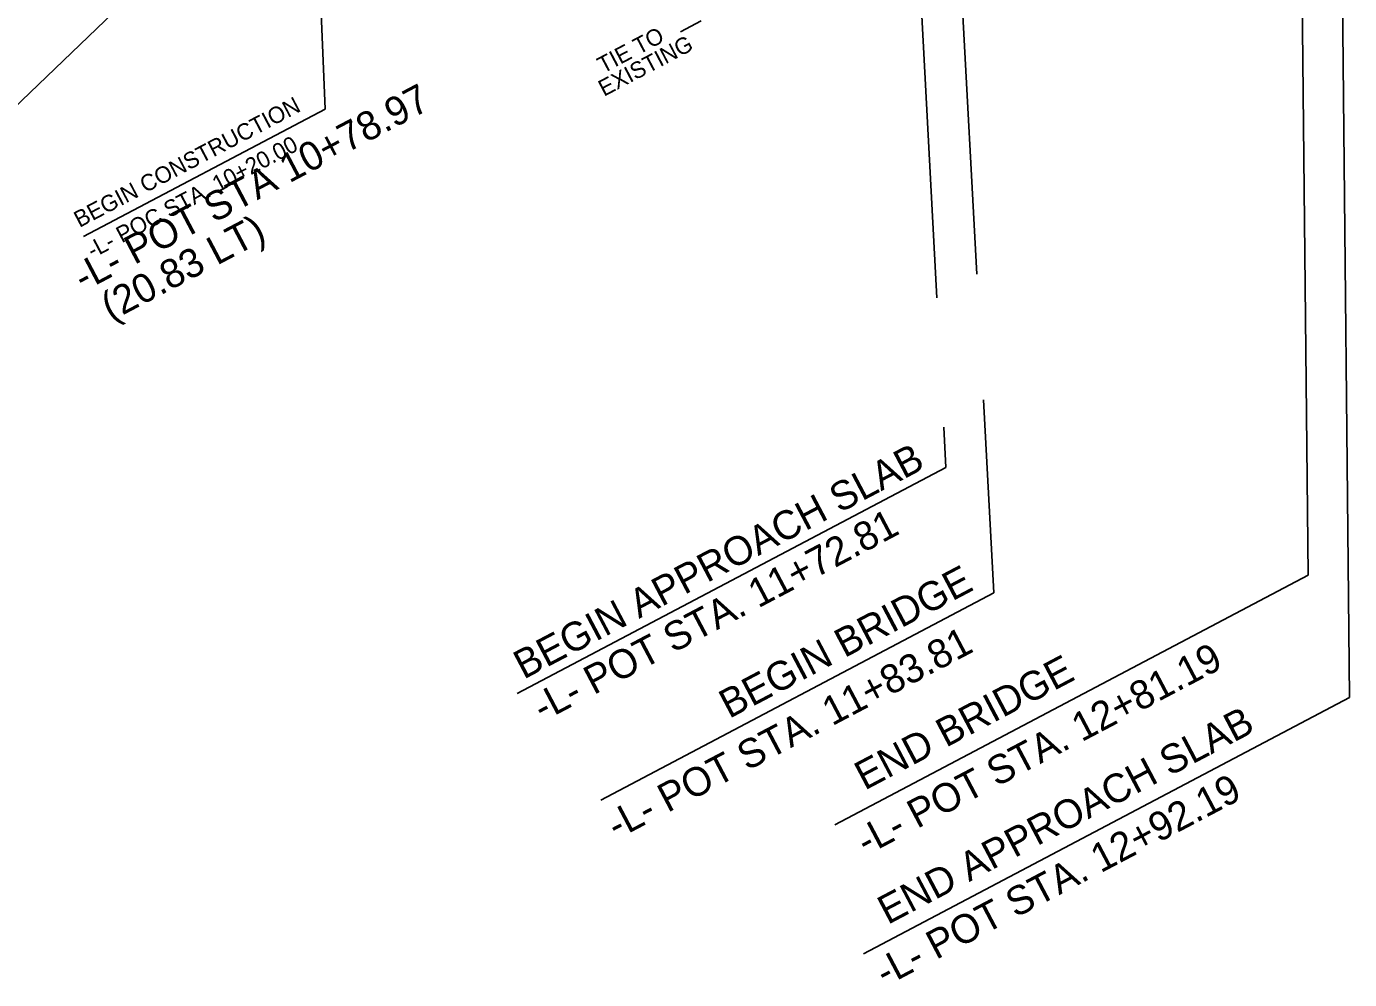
# Model space of a CAD drawing. Extents: x 1380803 to 1382221, y 595175 to 595787.
# Drawn here: x 1381403 to 1381725, y 595175.2 to 595407.2 of the extents above; entities that cross this region are included whole.
import ezdxf

# ---------------------------------------------------------------- set-up
doc = ezdxf.new("R2010")
doc.units = 0
for name, color, linetype in [('Prop Dimension', 7, 'Continuous'), ('Prop Horizontal Alignment Station Label', 7, 'Continuous'), ('Scratch_Level_0', 7, 'Continuous')]:
    doc.layers.add(name, color=color, linetype=linetype)

msp = doc.modelspace()

# ---------------------------------------------------------------- linework, layer by layer
at = {"layer": 'Prop Dimension'}
for p, q in [((1381475.64, 595387.03), (1381473.81, 595433.12)), ((1381567.14, 595408.57), (1381562.12, 595405.92)), ((1381416.87, 595356.05), (1381475.64, 595387.03))]:
    msp.add_line(p, q, dxfattribs=at)
at = {"layer": 'Prop Horizontal Alignment Station Label'}
for p, q in [((1381721.81, 595552.91), (1381724.97, 595243.87)), ((1381712.08, 595547.78), (1381714.88, 595273.61)), ((1381616.2, 595497.24), (1381624.54, 595341.15)), ((1381463.21, 595448.14), (1381386.67, 595374.68)), ((1381629.58, 595434.06), (1381634.24, 595346.9)), ((1381635.87, 595316.3), (1381638.38, 595269.3)), ((1381626.22, 595309.68), (1381626.74, 595299.86)), ((1381522.4, 595244.86), (1381626.74, 595299.86)), ((1381599.69, 595212.88), (1381714.88, 595273.61)), ((1381542.78, 595218.9), (1381638.38, 595269.3)), ((1381606.68, 595181.51), (1381724.97, 595243.87))]:
    msp.add_line(p, q, dxfattribs=at)

# ---------------------------------------------------------------- texts
at = {"layer": 'Prop Dimension'}
for s, p in [('TIE TO', (1381543.29, 595395.68)), ('EXISTING', (1381543.51, 595390.06)), ('BEGIN CONSTRUCTION', (1381415.87, 595358.15)), ('-L- POC STA. 10+20.00', (1381419.05, 595350.66))]:
    msp.add_text(s, height=4, rotation=27.7977, dxfattribs=at).set_placement(p)
at = {"layer": 'Prop Horizontal Alignment Station Label'}
for s, p in [('BEGIN APPROACH SLAB', (1381523.97, 595248.18)), ('-L- POT STA. 11+72.81', (1381528.6, 595237.87)), ('BEGIN BRIDGE', (1381573.99, 595238.62)), ('-L- POT STA. 11+83.81', (1381546.59, 595209.19)), ('-L- POT STA. 12+81.19', (1381607.32, 595205.3)), ('END BRIDGE', (1381606.97, 595221.17)), ('END APPROACH SLAB', (1381612.58, 595188.48)), ('-L- POT STA. 12+92.19', (1381611.94, 595173.4))]:
    msp.add_text(s, height=7, rotation=27.7977, dxfattribs=at).set_placement(p)
at = {"layer": 'Scratch_Level_0'}
for s, p in [('-L- POT STA 10+78.97', (1381416.8, 595342.56)), (' (20.83 LT) ', (1381421.23, 595334.15))]:
    msp.add_text(s, height=7, rotation=27.7977, dxfattribs=at).set_placement(p)

doc.saveas('drawing.dxf')
